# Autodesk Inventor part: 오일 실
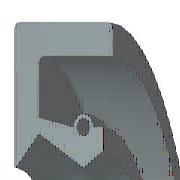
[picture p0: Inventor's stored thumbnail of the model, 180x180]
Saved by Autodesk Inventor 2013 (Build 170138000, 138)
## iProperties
Created: 2015-11
Part Number: 오일 실
Material: 고무
Description: 오일-실
Document SubType Name: Modeling
Standard: KS B 2804
Designer: mdu
Standards Organization: KS
Language: ko-KR
Size Designation: D - 10 20 7
Categories: <MemberInstance><Categories><Category DisplayName="샤프트 부품" InternalName="7f7aeb1f-a693-4053-b835-cee3144e0d98" Mnemonic="SHFT"><Category DisplayName="실링" Intern
Density: 0.93 g/cm^3
IsCustomPart: 0
Author: mdu
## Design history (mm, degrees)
revolve "본체" stored, may be unused: angle "d17" = 90 deg
revolve "스프링1" stored, may be unused: angle "d18" = 90 deg
body "Solid1"
sketch "스케치1"
  geometry: L1 (0, 10)-(7, 10); L2 (7, 8.25)-(1.75, 8.25); L3 (1.75, 6.75)-(4.9, 5); L4 (4.9, 5)-(0, 5); L5 (0, 0)-(9.586, 0) reference; L6 (4.9, 5)-(6.3, 5.875); L7 (0, 18)-(0, -3) reference; L8 (-1.941, 0)-(11.507, 0) reference; L9 (4.2, 7.1)-(1.75, 7.59); L10 (1.75, 7.59)-(1.75, 8.25); L11 (0, 10)-(0, 5.088); L12 (4.9, 5)-(0, 5); L13 (1.75, 6.75)-(0.152, 5.028); L14 (7, 10)-(7, 8.25); L15 (5.6, 7.1)-(6.3, 7.1); L16 (6.3, 7.1)-(6.3, 5.875); C1 r 0.455 at (4.9, 7.1); A1 r 0.7 centre (4.9, 7.1) between (5.6, 7.1) and (4.2, 7.1); A2 r 0.088 centre (0.088, 5.088) between (0, 5.088) and (0.152, 5.028); 1 further point
  constraints: 28 end point, 5 horizontal alignment, 5 point on line, 4 point on circle, 4 vertical alignment, 3 centre point, 3 tangent, 2 collinear, 2 horizontal, 2 perpendicular, 1 coincident, 1 parallel
  dimensions: "d0" = 20 diameter of L1 L5 (= SD2); "d1" = 1.75 distance of L1.end L2.start (= SD); "d2" = 0.91 diameter of C1 (= SPDI); "d3" = 1.4 diameter of A1 (= SPDA); "d4" = 10 diameter of L3.end L5 (= NND); "d5" = 13.5 diameter of L3.start L5 (= TKDM); "d7" = 15.18 diameter of L9.end L5 (= TKDM + 0.24 x SWDT); "d8" = 1.75 distance between parallel lines of L11 L10 (= SD); "d9" = 4.9 distance from line of L11 C1.centre (= SPDST); "d10" = 14.2 diameter of C1.centre L5 (= HLDM); "d11" = 0.0875 radius of A2 (= 0.25 x LAB); "d12" = 6.3 distance between parallel lines of L11 L16 (= SDI); "d13" = 11.75 diameter of L6.end L5 (= ABDM); "d14" = 7 distance from line of L11 L1.end (= SWDT)
fillet "모깎기1" dims "d6" = 0.3 (= RR)
other parameters: "SD2" = 20 [user parameter; used in 1 equation term], "SWDT" = 7 [user parameter; used in 2 equation terms], "RR" = 0.3 [user parameter; used in 1 equation term], "SD" = 1.75 [user parameter; used in 2 equation terms], "NND" = 10 [user parameter; used in 1 equation term], "SPDA" = 1.4 [user parameter; used in 1 equation term], "SPDI" = 0.91 [user parameter; used in 1 equation term], "TKDM" = 13.5 [user parameter; used in 2 equation terms], "HLDM" = 14.2 [user parameter; used in 1 equation term], "ABDM" = 11.75 [user parameter; used in 1 equation term], "SDI" = 6.3 [user parameter; used in 1 equation term], "SPDST" = 4.9 [user parameter; used in 1 equation term], "LAB" = 0.35 [user parameter; used in 1 equation term], "d15" = 0, "d16" = 0, "d19" = 0
